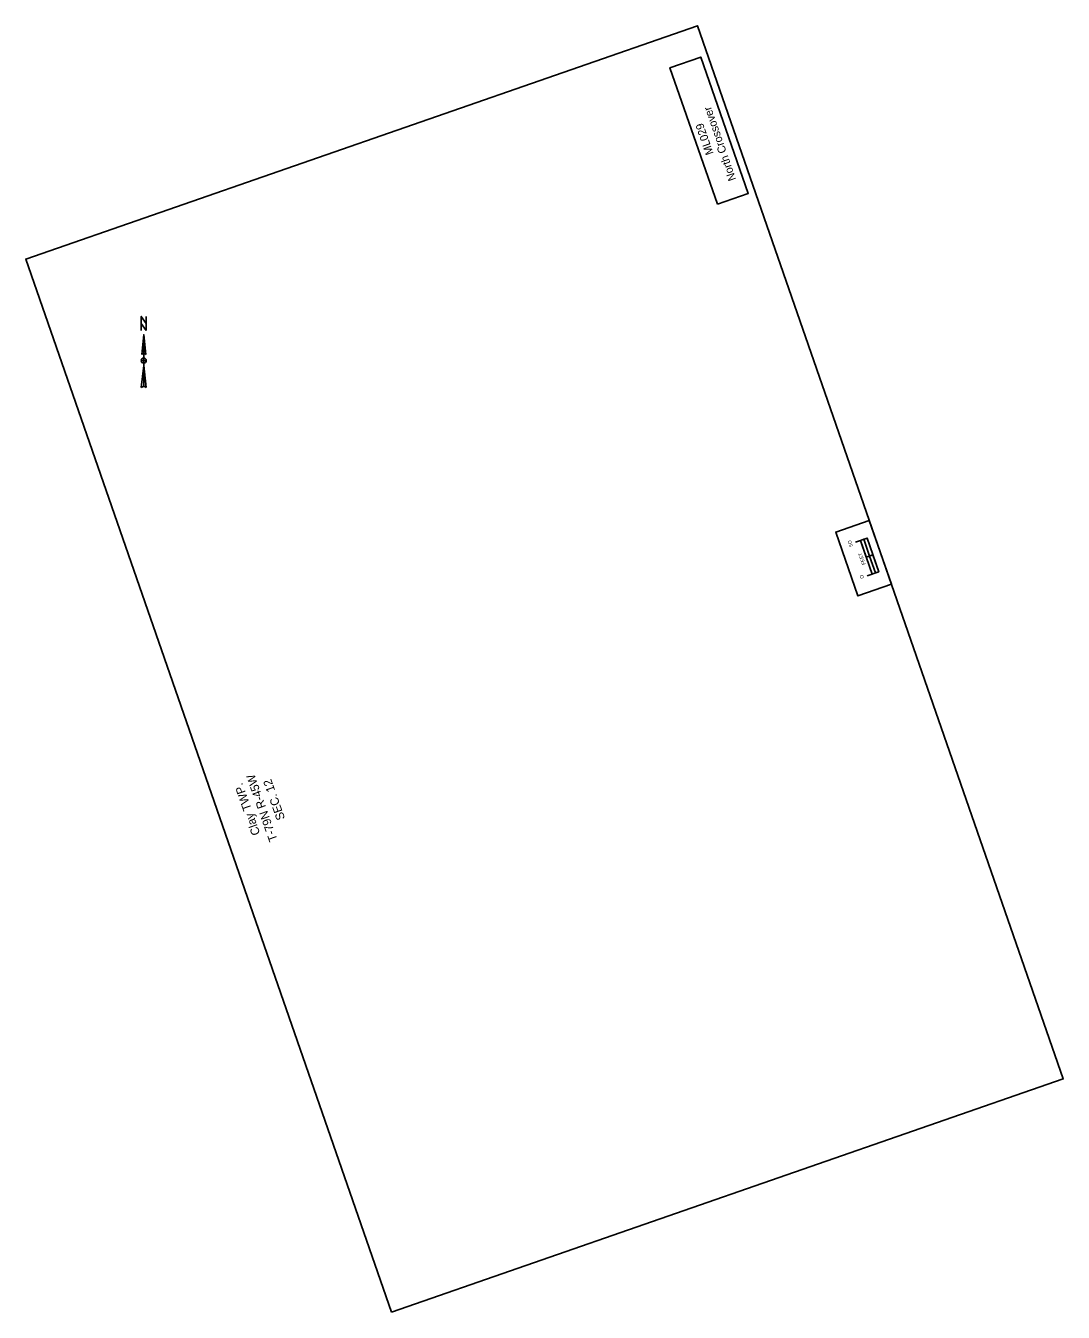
# Model space of a CAD drawing. Extents: x 16415719 to 16419955, y 7114623 to 7121273.
# Drawn here: x 16415719 to 16417178, y 7119464 to 7121273 of the extents above; entities that cross this region are included whole.
import ezdxf

# ---------------------------------------------------------------- set-up
doc = ezdxf.new("R2010")
doc.units = 0
for name, color, linetype in [('NamedBoundary', 7, 'Continuous'), ('SheetBorder', 7, 'Continuous'), ('SheetGridMajor', 7, 'Continuous')]:
    doc.layers.add(name, color=color, linetype=linetype)

msp = doc.modelspace()

# ---------------------------------------------------------------- linework, layer by layer
at = {"layer": 'NamedBoundary'}
msp.add_lwpolyline([(16416233.1, 7119464), (16417177.7, 7119792.1), (16416663.5, 7121272.8), (16415718.8, 7120944.7)], close=True, dxfattribs=at)
at = {"layer": 'SheetBorder'}
msp.add_line((16416910.2, 7120528.8), (16416900.8, 7120525.5), dxfattribs=at)
msp.add_line((16416910.2, 7120528.8), (16416900.8, 7120525.5), dxfattribs=at)
for points in [[(16416691.4, 7121021.7), (16416624.7, 7121213.8), (16416668, 7121228.8), (16416734.7, 7121036.8)], [(16416889, 7120471.2), (16416857.8, 7120560.9), (16416905, 7120577.3), (16416936.2, 7120487.6)], [(16416889, 7120471.2), (16416857.8, 7120560.9), (16416905, 7120577.3), (16416936.2, 7120487.6)], [(16416936.2, 7120487.6), (16416889, 7120471.2), (16416857.8, 7120560.9), (16416905, 7120577.3)], [(16416905.5, 7120527.2), (16416897.3, 7120550.8), (16416892.6, 7120549.2), (16416900.8, 7120525.5)], [(16416918.4, 7120505.2), (16416910.2, 7120528.8), (16416905.5, 7120527.2), (16416913.7, 7120503.5)]]:
    msp.add_lwpolyline(points, close=True, dxfattribs=at)
for points in [[(16416901.9, 7120499.5), (16416918.4, 7120505.2), (16416902, 7120552.4), (16416885.5, 7120546.7)], [(16416909, 7120501.9), (16416892.6, 7120549.2)]]:
    msp.add_lwpolyline(points, dxfattribs=at)
at = {"layer": 'SheetGridMajor'}
for p, q in [((16415884.8, 7120838.6), (16415887.6, 7120810.5)), ((16415884.8, 7120838.6), (16415884.8, 7120765.4)), ((16415882, 7120810.5), (16415882, 7120810.5)), ((16415882.1, 7120810.7), (16415882.6, 7120811.3)), ((16415881.3, 7120764), (16415884.8, 7120795)), ((16415884.8, 7120798.5), (16415884.8, 7120798.5))]:
    msp.add_line(p, q, dxfattribs=at)
msp.add_lwpolyline([(16415888.3, 7120844.3), (16415881.3, 7120854.1), (16415881.3, 7120864), (16415888.3, 7120854.1)], close=True, dxfattribs=at)
for points in [[(16415881.3, 7120844.3), (16415881.3, 7120864), (16415888.3, 7120854.1), (16415888.3, 7120864)], [(16415882, 7120810.5), (16415884.8, 7120838.6), (16415884.8, 7120811.9)], [(16415884.8, 7120798.5), (16415884.8, 7120802), (16415881.3, 7120802)], [(16415888.3, 7120802), (16415884.8, 7120802), (16415884.8, 7120805.6)], [(16415884.8, 7120765.4), (16415884.8, 7120795), (16415888.3, 7120764)]]:
    msp.add_lwpolyline(points, dxfattribs=at)
for centre, radius, start, end in [((16415884.8, 7120808.4), 3.52, 90.0201, 143.1255), ((16415884.8, 7120808.4), 3.52, 36.8478, 90.0216), ((16415884.8, 7120802), 3.52, 89.9997, 179.9997), ((16415884.8, 7120802), 3.52, 179.9997, 269.9997), ((16415884.8, 7120802), 3.52, 359.9997, 89.9997), ((16415884.8, 7120802), 3.52, 269.9997, 359.9997), ((16415884.8, 7120760.3), 5.1, 89.9891, 133.6187), ((16415884.8, 7120760.3), 5.11, 46.4018, 90.0004)]:
    msp.add_arc(centre, radius, start, end, dxfattribs=at)

# ---------------------------------------------------------------- texts
at = {"layer": 'SheetBorder'}
for s, height, rotation, p in [('North Crossover', 11.25, 109.1528, (16416717.9, 7121056.8)), ('ML029 ', 11.25, 109.1528, (16416686.1, 7121093.4)), ('5O', 5, 109.1528, (16416882.1, 7120541.2)), ('FEET', 5, 109.1528, (16416899.9, 7120515.7)), ('O', 5, 109.1528, (16416897.7, 7120496.3)), ('T-79N R-45W', 12, 109.415, (16416073, 7120128.2)), ('SEC. 12', 12, 109.415, (16416083.6, 7120158.3)), ('Clay TWP.', 12, 109.415, (16416048.7, 7120136.9))]:
    msp.add_text(s, height=height, rotation=rotation, dxfattribs=at).set_placement(p)

doc.saveas('drawing.dxf')
